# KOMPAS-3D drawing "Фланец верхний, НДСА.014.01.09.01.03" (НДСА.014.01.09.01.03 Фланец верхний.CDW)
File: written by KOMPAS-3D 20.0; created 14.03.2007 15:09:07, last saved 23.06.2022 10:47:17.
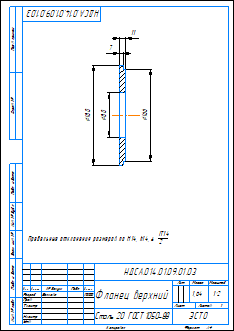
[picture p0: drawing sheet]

Sheet 1: A4, portrait

Document properties: Автор: Устинов А.В.; Организация: ЭСТО-Вакуум; Полное имя файла: НДСА.014.01.09.01.03 Фланец верхний.m3d; 281758021878: <item xmlns="http://appius.ru/pdm" xmlns:xs="http://www.w3.org/2001/XMLSchema" xmlns:xsi="http://www.w3.org/2001/XMLSchema-instance" xsi:type="item">  <element xmlns:d2p1="http://v8.1c.ru/8.1/data/enterprise/current-config" xsi:type="d2p1:CatalogRef.aps_Элемен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; PLM_CDWXDTO: <item xmlns="http://appius.ru/pdm" xmlns:xs="http://www.w3.org/2001/XMLSchema" xmlns:xsi="http://www.w3.org/2001/XMLSchema-instance" xsi:type="item">  <element xmlns:d2p1="http://v8.1c.ru/8.1/data/enterprise/current-config" xsi:type="d2p1:CatalogRef.aps_Элемен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; Масса: 1.63755

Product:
- Part/product: Фланец верхний  | designation НДСА.014.01.09.01.03
    Материал: Сталь 20  ГОСТ 1050-88 (density 7820 kg/m3)
    Масса: 1.63755

Title block, sheet 1: Наименование: Фланец верхний; designation: НДСА.014.01.09.01.03; Материал: Сталь 20  ГОСТ 1050-88; Масса: 1,64; scale: 1:2; Количество листов документа: 1; organisation: ЭСТО; Форматы листов документа: A4; stored path: D:\Шлейф\УКРД.762.10.00.00.00 Верхняя стойка\УКРД.762.10.01.00.02 Фланец верхний.cdw; Разработал: Волкова; Разработал, date: 17.01.2020
Table, sheet 1:
  0;Material:V399CD8922A934364BF9D3DB1A16B3F75;Sortament:V4CE53C8DF9054128977D0077DE50C5F6^SortamentEx:VBB974A3EA50F43AE83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

Views: Вид 1, Сверху, Разрез А-А
Referenced files in E:\НДСА.014.01.09.00.00 Верхняя стойка гидроподъемника\: НДСА.014.01.09.01.03 Фланец верхний.m3d
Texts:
  НДСА.014.01.09.01.03 Фланец верхний
Dimensions and other numbers on the sheet: 166; 80; 180; 11; 7; 1:2; 1; 1,64; 17.01.2020

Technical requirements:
  Предельные отклонения размеров по H14, h14,    IT14 2 .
